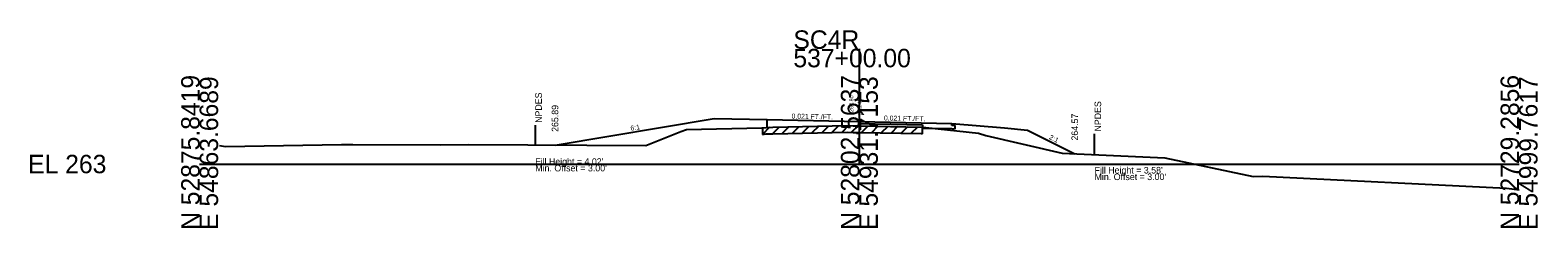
# Model space of a CAD drawing. Extents: x 7498 to 13027, y 90095 to 109625.
# Drawn here: x 9498.3 to 9726.8, y 107095.5 to 107125.5 of the extents above; entities that cross this region are included whole.
import ezdxf

# ---------------------------------------------------------------- set-up
doc = ezdxf.new("R2010")
doc.units = 0
for name, color, linetype in [('Level 10', 7, 'Continuous'), ('Level 11', 7, 'Continuous'), ('Level 12', 7, 'Continuous'), ('Level 32', 7, 'Continuous'), ('Level 33', 7, 'Continuous'), ('Level 50', 7, 'Continuous'), ('Level 53', 7, 'Continuous'), ('Level 55', 7, 'Continuous'), ('Level 59', 7, 'Continuous'), ('Level 6', 7, 'Continuous'), ('Level 60', 7, 'Continuous'), ('Level 61', 7, 'Continuous'), ('Level 63', 7, 'Continuous'), ('Level 7', 7, 'Continuous')]:
    doc.layers.add(name, color=color, linetype=linetype)

msp = doc.modelspace()

# ---------------------------------------------------------------- linework, layer by layer
at = {"layer": 'Level 11'}
for p, q in [((9609.99, 107110.72), (9609.99, 107111.9)), ((9637.99, 107111.02), (9637.99, 107111.32)), ((9638.49, 107111), (9637.99, 107111.02)), ((9637.99, 107110.54), (9638.49, 107110.52)), ((9638.49, 107110.52), (9638.49, 107111))]:
    msp.add_line(p, q, dxfattribs=at)
at = {"layer": 'Level 12'}
for p, q in [((9633.55, 107110.76), (9633.55, 107110.63)), ((9633.55, 107110.63), (9637.99, 107110.54))]:
    msp.add_line(p, q, dxfattribs=at)
at = {"layer": 'Level 53'}
for p, q in [((9623.99, 107111.31), (9633.55, 107111.11)), ((9633.55, 107111.11), (9633.55, 107110.76))]:
    msp.add_line(p, q, dxfattribs=at)
at = {"layer": 'Level 55'}
for p, q in [((9574.86, 107111.04), (9574.86, 107108.04)), ((9659.64, 107106.72), (9659.64, 107109.72))]:
    msp.add_line(p, q, dxfattribs=at)
at = {"layer": 'Level 59'}
for p, q in [((9609.99, 107111.9), (9623.99, 107111.61)), ((9623.99, 107111.61), (9637.99, 107111.32))]:
    msp.add_line(p, q, dxfattribs=at)
at = {"layer": 'Level 6'}
for p, q in [((9601.99, 107112.06), (9609.99, 107111.9)), ((9637.99, 107111.32), (9645.99, 107110.65)), ((9645.99, 107110.65), (9649.49, 107110.3))]:
    msp.add_line(p, q, dxfattribs=at)
at = {"layer": 'Level 60'}
for p, q in [((9591.6, 107107.97), (9596.93, 107110.1)), ((9596.93, 107110.1), (9597.77, 107110.41)), ((9597.77, 107110.41), (9609.21, 107110.64)), ((9609.21, 107110.64), (9609.86, 107110.72)), ((9609.86, 107110.72), (9610.88, 107110.75)), ((9610.88, 107110.75), (9622.14, 107110.99)), ((9622.14, 107110.99), (9623.05, 107110.97)), ((9623.05, 107110.97), (9623.99, 107110.96)), ((9623.99, 107110.96), (9633.42, 107110.77)), ((9633.42, 107110.77), (9634.08, 107110.69)), ((9634.08, 107110.69), (9642.06, 107109.84)), ((9642.06, 107109.84), (9643.15, 107109.51)), ((9527, 107107.99), (9527.93, 107107.81)), ((9527.93, 107107.81), (9545.48, 107108.11)), ((9545.48, 107108.11), (9547.22, 107108.14)), ((9547.22, 107108.14), (9560.56, 107108.08)), ((9560.56, 107108.08), (9564.79, 107108.11)), ((9564.79, 107108.11), (9591.6, 107107.97)), ((9643.15, 107109.51), (9654.71, 107106.81)), ((9654.71, 107106.81), (9668.08, 107106.18)), ((9668.08, 107106.18), (9670.3, 107106.1)), ((9670.3, 107106.1), (9683.68, 107103.28)), ((9683.68, 107103.28), (9685.16, 107103.31)), ((9685.16, 107103.31), (9722.06, 107101.48)), ((9722.06, 107101.48), (9722.87, 107101.4)), ((9722.87, 107101.4), (9723.99, 107101.23))]:
    msp.add_line(p, q, dxfattribs=at)
at = {"layer": 'Level 61'}
for p, q in [((9610.39, 107110.74), (9609.3, 107109.65)), ((9609.3, 107110.65), (9609.3, 107109.65)), ((9611.82, 107110.77), (9610.8, 107109.75)), ((9610.88, 107109.75), (9622.14, 107109.99)), ((9613.32, 107110.8), (9612.3, 107109.78)), ((9614.83, 107110.83), (9613.8, 107109.81)), ((9616.33, 107110.87), (9615.3, 107109.84)), ((9617.83, 107110.9), (9616.8, 107109.88)), ((9619.33, 107110.93), (9618.3, 107109.91)), ((9620.83, 107110.96), (9619.81, 107109.94)), ((9622.32, 107110.99), (9621.31, 107109.97)), ((9622.14, 107109.99), (9623.05, 107109.97)), ((9623.79, 107110.96), (9622.81, 107109.98)), ((9623.05, 107109.97), (9623.99, 107109.96)), ((9623.99, 107109.96), (9633.42, 107109.77)), ((9625.29, 107110.93), (9624.31, 107109.95)), ((9626.79, 107110.9), (9625.81, 107109.92)), ((9628.29, 107110.87), (9627.31, 107109.89)), ((9629.79, 107110.84), (9628.81, 107109.86)), ((9631.29, 107110.81), (9630.31, 107109.83)), ((9632.79, 107110.78), (9631.81, 107109.8)), ((9633.55, 107109.76), (9633.55, 107110.76)), ((9609.3, 107109.65), (9609.86, 107109.72)), ((9609.86, 107109.72), (9610.88, 107109.75)), ((9633.42, 107109.77), (9633.55, 107109.76))]:
    msp.add_line(p, q, dxfattribs=at)
at = {"layer": 'Level 63'}
for p, q in [((9623.99, 107105.16), (9623.99, 107122.65)), ((9523.99, 107105.16), (9623.99, 107105.16)), ((9623.99, 107105.16), (9723.99, 107105.16))]:
    msp.add_line(p, q, dxfattribs=at)
at = {"layer": 'Level 7'}
for p, q in [((9577.86, 107108.04), (9601.99, 107112.06)), ((9649.49, 107110.3), (9656.64, 107106.72))]:
    msp.add_line(p, q, dxfattribs=at)

# ---------------------------------------------------------------- texts
at = {"layer": 'Level 10'}
msp.add_text('268.80', height=0.6, rotation=90, dxfattribs=at).set_placement((9623.08, 107113.05))
at = {"layer": 'Level 32'}
for s, rotation, p in [('0.021 FT./FT.', 358.8084, (9613.71, 107112.07)), ('0.021 FT./FT.', 358.8084, (9627.71, 107111.78)), ('6:1', 9.4623, (9589.36, 107110.21)), ('2:1', 333.435, (9652.67, 107108.99))]:
    msp.add_text(s, height=0.75, rotation=rotation, dxfattribs=at).set_placement(p)
at = {"layer": 'Level 33'}
for s, p in [('265.89', (9578.36, 107110.04)), ('264.57', (9657.14, 107108.72))]:
    msp.add_text(s, height=1, rotation=90, dxfattribs=at).set_placement(p)
at = {"layer": 'Level 50'}
for p in [(9575.86, 107111.04), (9660.64, 107109.72)]:
    msp.add_text(' NPDES', height=1, rotation=90, dxfattribs=at).set_placement(p)
for s, p in [("Fill Height = 4.02' ", (9574.86, 107105.04)), ("Min. Offset = 3.00' ", (9574.86, 107104.04)), ("Fill Height = 3.58' ", (9659.64, 107103.72)), ("Min. Offset = 3.00' ", (9659.64, 107102.72))]:
    msp.add_text(s, height=1, dxfattribs=at).set_placement(p)
at = {"layer": 'Level 59'}
msp.add_text(' 269.45', height=0.6, rotation=90, dxfattribs=at).set_placement((9624.34, 107112.38))
at = {"layer": 'Level 63'}
for s, p in [('SC4R', (9613.99, 107122.65)), ('537+00.00', (9613.99, 107119.85)), ('EL 263', (9497.99, 107103.76))]:
    msp.add_text(s, height=2.8, dxfattribs=at).set_placement(p)
for s, p in [('N 52875.8419', (9523.99, 107095.16)), ('E 54863.6689', (9526.79, 107095.16)), ('N 52802.5637', (9623.99, 107095.16)), ('E 54931.7153', (9626.79, 107095.16)), ('N 52729.2856', (9723.99, 107095.16)), ('E 54999.7617', (9726.79, 107095.16))]:
    msp.add_text(s, height=2.8, rotation=90, dxfattribs=at).set_placement(p)

doc.saveas('drawing.dxf')
